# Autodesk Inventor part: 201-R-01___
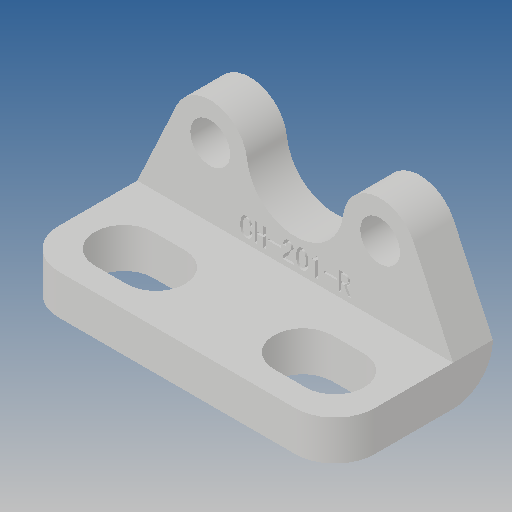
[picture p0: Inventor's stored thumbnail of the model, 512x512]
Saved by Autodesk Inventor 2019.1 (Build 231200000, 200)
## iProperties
Created: 2010-06
Part Number: 201-R-01___
Material: Ogólny
Document SubType Name: Modeling
Designer: CADENGINEERING4
Density: 1 g/cm^3
Appearance: Domyślna
Author: CADENGINEERING4
Revision Number: ANY
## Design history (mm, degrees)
feature "NONE"
node "Bryła1"
